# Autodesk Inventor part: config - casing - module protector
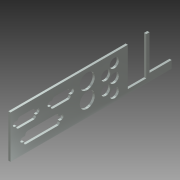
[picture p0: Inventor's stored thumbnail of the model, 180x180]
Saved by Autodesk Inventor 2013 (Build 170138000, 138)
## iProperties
Company: Autodesk Inc.
Created: 2005-12
Part Number: config - casing - module protector
Document SubType Name: Modeling
Designer: Autodesk Inc.
Stock Number: config - casing - module protector
Density: 1 g/cm^3
Mass: 6.64671 g
Surface Area: 84.1526 cm^2
Volume: 6.64671 cm^3
Material: Allgemein
Title: PC Demo
Author: Autodesk Inc.
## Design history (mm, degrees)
sketch "Sketch2"
  geometry: L1 (-2.5, 55.99)-(-2.5, 18.99); L2 (-2.5, 18.99)-(-150.5, 18.99); L3 (-150.5, 18.99)-(-150.5, 55.99); L4 (-150.5, 55.99)-(-2.5, 55.99); L5 (87, 57.49)-(-160.5, 57.49); L6 (-151, 57.49)-(-2, 57.49); L7 (-2, 57.49)-(-2, 17.99); L8 (-2, 17.99)-(-151, 17.99); L9 (-151, 17.99)-(-151, 57.49)
  constraints: 18 end point, 2 parallel, 1 horizontal, 1 perpendicular, 1 point on line
  dimensions: "d1" = 1.5 distance between parallel lines of L5 L4 (derived); "d2" = 0.5 distance between parallel lines of L1 L7; "d3" = 0.5 distance between parallel lines of L3 L9; "d4" = 1 distance between parallel lines of L8 L2
extrude "Extrusion1" new body sketch "Sketch2" distance "d5" = 2; taper "d6" = 0 deg
sketch "Sketch3"
  geometry: L1 (111.207, 48.265)-(112.636, 43.265) reference; L2 (98.754, 48.99)-(110.246, 48.99) reference; L3 (96.364, 43.265)-(97.793, 48.265) reference; L4 (111.674, 41.99)-(97.326, 41.99) reference; L5 (143.674, 41.99)-(129.326, 41.99) reference; L6 (128.364, 43.265)-(129.793, 48.265) reference; L7 (130.754, 48.99)-(142.246, 48.99) reference; L8 (143.207, 48.265)-(144.636, 43.265) reference; L9 (108.781, 33.99)-(135.219, 33.99) reference; L10 (106.311, 27.233)-(107.811, 33.233) reference; L11 (136.719, 25.99)-(107.281, 25.99) reference; L12 (136.189, 33.233)-(137.689, 27.233) reference; L13 (95.403, 43.539)-(96.831, 48.539); L14 (98.754, 49.99)-(110.246, 49.99); L15 (112.169, 48.539)-(113.597, 43.539); L16 (111.674, 40.99)-(97.326, 40.99); L17 (94.143, 47.99)-(96.674, 47.99); L18 (94.143, 43.99)-(95.531, 43.99); L19 (114.857, 47.99)-(112.326, 47.99); L20 (114.857, 43.99)-(113.469, 43.99); L21 (142.246, 49.99)-(130.754, 49.99); L22 (128.831, 48.539)-(127.403, 43.539); L23 (129.326, 40.99)-(143.674, 40.99); L24 (145.597, 43.539)-(144.169, 48.539); L25 (126.143, 47.99)-(128.674, 47.99); L26 (126.143, 43.99)-(127.531, 43.99); L27 (146.857, 47.99)-(144.326, 47.99); L28 (146.857, 43.99)-(145.469, 43.99); L29 (135.219, 34.99)-(108.781, 34.99); L30 (106.84, 33.475)-(105.34, 27.475); L31 (107.281, 24.99)-(136.719, 24.99); L32 (138.66, 27.475)-(137.16, 33.475); L33 (104, 31.99)-(106.469, 31.99); L34 (104, 27.99)-(105.469, 27.99); L35 (140, 31.99)-(137.531, 31.99); L36 (140, 27.99)-(138.531, 27.99); C1 r 0.792 at (114.857, 45.99) reference; C2 r 0.792 at (94.143, 45.99) reference; C3 r 0.792 at (146.857, 45.99) reference; C4 r 0.792 at (126.143, 45.99) reference; C5 r 0.792 at (140, 29.99) reference; C6 r 0.792 at (104, 29.99) reference; A1 r 1 centre (111.674, 42.99) between (111.674, 41.99) and (112.636, 43.265) reference; A2 r 1 centre (110.246, 47.99) between (111.207, 48.265) and (110.246, 48.99) reference; A3 r 1 centre (98.754, 47.99) between (98.754, 48.99) and (97.793, 48.265) reference; A4 r 1 centre (97.326, 42.99) between (96.364, 43.265) and (97.326, 41.99) reference; A5 r 1 centre (129.326, 42.99) between (128.364, 43.265) and (129.326, 41.99) reference; A6 r 1 centre (130.754, 47.99) between (130.754, 48.99) and (129.793, 48.265) reference; A7 r 1 centre (142.246, 47.99) between (143.207, 48.265) and (142.246, 48.99) reference; A8 r 1 centre (143.674, 42.99) between (143.674, 41.99) and (144.636, 43.265) reference; A9 r 1 centre (108.781, 32.99) between (108.781, 33.99) and (107.811, 33.233) reference; A10 r 1 centre (107.281, 26.99) between (106.311, 27.233) and (107.281, 25.99) reference; A11 r 1 centre (136.719, 26.99) between (136.719, 25.99) and (137.689, 27.233) reference; A12 r 1 centre (135.219, 32.99) between (136.189, 33.233) and (135.219, 33.99) reference; A13 r 2 centre (97.326, 42.99) between (95.403, 43.539) and (97.326, 40.99); A14 r 2 centre (98.754, 47.99) between (98.754, 49.99) and (96.831, 48.539); A15 r 2 centre (110.246, 47.99) between (112.169, 48.539) and (110.246, 49.99); A16 r 2 centre (111.674, 42.99) between (111.674, 40.99) and (113.597, 43.539); A17 r 2 centre (94.143, 45.99) between (94.143, 47.99) and (94.143, 43.99); A18 r 2 centre (114.857, 45.99) between (114.857, 47.99) and (114.857, 43.99); A19 r 2 centre (126.143, 45.99) between (126.143, 47.99) and (126.143, 43.99); A20 r 2 centre (146.857, 45.99) between (146.857, 47.99) and (146.857, 43.99); A21 r 2 centre (140, 29.99) between (140, 31.99) and (140, 27.99); A22 r 2 centre (104, 29.99) between (104, 31.99) and (104, 27.99); A23 r 2 centre (130.754, 47.99) between (130.754, 49.99) and (128.831, 48.539); A24 r 2 centre (129.326, 42.99) between (127.403, 43.539) and (129.326, 40.99); A25 r 2 centre (143.674, 42.99) between (143.674, 40.99) and (145.597, 43.539); A26 r 2 centre (142.246, 47.99) between (144.169, 48.539) and (142.246, 49.99); A27 r 2 centre (108.781, 32.99) between (108.781, 34.99) and (106.84, 33.475); A28 r 2 centre (107.281, 26.99) between (105.34, 27.475) and (107.281, 24.99); A29 r 2 centre (136.719, 26.99) between (136.719, 24.99) and (138.66, 27.475); A30 r 2 centre (135.219, 32.99) between (137.16, 33.475) and (135.219, 34.99)
  constraints: 72 end point, 60 point on circle, 36 centre point, 12 parallel, 12 point on line, 12 tangent, 6 coincident, 6 horizontal, 5 equal radius, 87 other
  dimensions: "d7" = 1 distance between parallel lines of L2 L14; "d8" = 4 diameter of A17; "d9" = 1 distance between parallel lines of L7 L21 (= d7); "d10" = 1 distance between parallel lines of L9 L29 (= d7)
extrude "Extrusion2" cut sketch "Sketch3" stored distance "d11" = 10; taper "d12" = 0 deg
sketch "Sketch4"
  geometry: C1 r 3.5 at (55, 48.99) reference; C2 r 3.5 at (63, 42.99) reference; C3 r 3.5 at (55, 36.99) reference; C4 r 3.5 at (63, 30.99) reference; C5 r 3.5 at (55, 24.99) reference; C6 r 6 at (80, 46.99) reference; C7 r 6 at (80, 31.99) reference; C8 r 4.25 at (55, 48.99); C9 r 4.25 at (63, 42.99); C10 r 4.25 at (55, 36.99); C11 r 4.25 at (55, 24.99); C12 r 4.25 at (63, 30.99); C13 r 7 at (80, 31.99); C14 r 7 at (80, 46.99)
  constraints: 14 centre point, 7 coincident, 5 equal radius, 14 other
  dimensions: "d13" = 8.5 diameter of C8; "d14" = 14 diameter of C14
extrude "Extrusion3" cut sketch "Sketch4" stored distance "d15" = 10; taper "d16" = 0 deg
sketch "Sketch5"
  geometry: L1 (2, 57.49)-(151, 57.49) reference; L2 (2, 17.99)-(2, 57.49) reference; L3 (2, 24.99)-(22.5, 24.99); L4 (22.5, 24.99)-(22.5, 57.49); L5 (22.5, 57.49)-(2, 57.49); L6 (2, 57.49)-(2, 24.99); L7 (25.5, 21.99)-(42.5, 21.99); L8 (42.5, 21.99)-(42.5, 57.49); L9 (42.5, 57.49)-(25.5, 57.49); L10 (25.5, 57.49)-(25.5, 21.99); L11 (151, 17.99)-(2, 17.99) reference
  constraints: 16 end point, 4 parallel, 3 point on line, 2 horizontal, 2 perpendicular
  dimensions: "d24" = 4 distance between parallel lines of L11 L7; "d25" = 7 distance between parallel lines of L11 L3; "d26" = 20.5 distance of L3.start L3.end; "d27" = 3 distance between parallel lines of L10 L4; "d28" = 17 distance between parallel lines of L8 L10
extrude "Extrusion4" cut sketch "Sketch5" stored distance "d22" = 10; taper "d23" = 0 deg
body "Solid1"
